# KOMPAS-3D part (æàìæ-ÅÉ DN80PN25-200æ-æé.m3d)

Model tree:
1. Объединить компоненты:1  (labels: СЕНС-ПР DN80PN25-200С)
2. Эскиз:1
3. Операция выдавливания:1
     Расстояние 1 = 14
4. Фаска:1
     Угол = 45; Длина 1 = 2; Длина 2 = 2

Referenced files in D:\Савин\!СЕНСОР\3D для заказчика\!Новый перечень\СЕНС-ПР\2. СЕНС-ПР-200С\DN80\: СЕНС-ПР DN80PN25-200С.a3d
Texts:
  СЕНС-ПР DN80PN25-200С-СВ
  ООО НПП Сенсор
  СЕНС-ПР DN80PN25-200С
